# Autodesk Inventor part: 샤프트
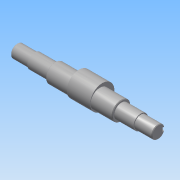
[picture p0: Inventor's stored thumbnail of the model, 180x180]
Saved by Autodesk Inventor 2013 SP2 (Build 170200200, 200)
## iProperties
Created: 2013-06
Part Number: 샤프트
Document SubType Name: Modeling
Designer: SeoGD™[esajin.kr]
Density: 7.86 g/cm^3
Material: 강철, 연강
Mass: 1327.93 g
Surface Area: 248.524 cm^2
Volume: 168.947 cm^3
Author: SeoGD™[esajin.kr]
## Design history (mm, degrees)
sketch "스케치1"
  geometry: L1 (-20.5, -41.331)-(-20.5, 32.669) reference; L2 (7.5, -30.031)-(7.5, 21.369) reference; L3 (135.5, -30.331)-(135.5, 21.669) reference; L4 (121.5, 21.369)-(121.5, -30.031) reference; L5 (184.5, -4.331)-(-57.5, -4.331); L6 (184.5, -4.331)-(184.5, 6.669); L7 (154.5, 8.169)-(121.5, 8.169); L8 (121.5, 8.169)-(121.5, 11.669); L9 (121.5, 11.669)-(7.5, 11.669); L10 (7.5, 11.669)-(7.5, 8.169); L11 (7.5, 8.169)-(-27.5, 8.169); L12 (-27.5, 8.169)-(-27.5, 6.669); L13 (-27.5, 6.669)-(-57.5, 6.669); L14 (-57.5, 6.669)-(-57.5, -4.331); L15 (154.5, 8.169)-(154.5, 6.669); L16 (154.5, 6.669)-(184.5, 6.669); C1 r 32.5 at (64.5, -4.331) reference; 1 further point
  constraints: 24 end point, 8 perpendicular, 5 point on line, 3 parallel, 2 collinear
  dimensions: "d1" = 25 diameter of L11 L5; "d2" = 32 diameter of L9 L5; "d3" = 22 diameter of L13 L5; "d4" = 35 distance of L10.end L11.end; "d5" = 30 distance of L12.end L13.end; "d15" = 33 distance of L7.start L7.end; "d26" = 30 distance of L15.end L6.end
revolve "회전1" sketch "스케치1" stored, may be unused: angle "d6" = 90 deg
node "작업 평면1"
sketch "스케치2"
  geometry: C1 r 16 at (0, 0) reference; C2 r 16 at (0, 0) reference; C3 r 20.75 at (0, 4); C4 r 16 at (0, 0) reference; 1 further point
  constraints: 1 centre point, 1 vertical alignment
  dimensions: "d8" = 41.5 diameter of C3; "d25" = 4 distance of C3.centre C1.centre
extrude "돌출1" join sketch "스케치2" stored distance "d9" = 40; taper "d10" = 0 deg
chamfer "모따기1" distance "d11" = 1; stored, may be unused: second distance "d12" = 2, angle "d13" = 45 deg
node "작업 평면2"
sketch "스케치3"
  geometry: L1 (-15, -10)-(-15, 10) reference; L2 (-15, 3)-(0, 3); L3 (0, -3)-(-15, -3); A1 r 3 centre (0, 0) between (0, -3) and (0, 3); 2 further points
  constraints: 4 end point, 2 perpendicular, 2 point on circle, 2 point on line, 2 tangent, 1 centre point, 1 horizontal alignment, 1 midpoint
  dimensions: "d16" = 18 dimension on A1 L1; "d17" = 6 distance between parallel lines of L3 L2
extrude "돌출2" cut sketch "스케치3" distance "d18" = 3.5; taper "d19" = 0 deg
node "작업 평면3"
node "솔리드1"
mirror "대칭1"
node "참조1"
node "참조2"
node "참조3"
node "참조4"
node "참조5"
node "투영된 루프1"
